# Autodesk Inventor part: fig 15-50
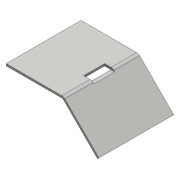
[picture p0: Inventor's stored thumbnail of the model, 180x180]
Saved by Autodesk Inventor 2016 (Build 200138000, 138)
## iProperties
Created: 2015-07
Part Number: fig 15-50
Material: Generic
Document SubType Name: Sheet Metal
Designer: Sandeep
Density: 1 g/cm^3
Sheet Metal Rule: Default_mm
Appearance: Default
Author: Sandeep
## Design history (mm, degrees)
node "Face1"
  sketch "Sketch1"
    geometry: L1 (-9.283, 8.313)-(4.503, 8.313); L2 (4.503, 8.313)-(4.503, -9.63); L3 (4.503, -9.63)-(-9.283, -9.63); L4 (-9.283, -9.63)-(-9.283, 8.313); 1 further point
    constraints: 8 end point, 2 parallel, 1 horizontal, 1 perpendicular
node "Flange1"
sketch "Sketch3"
  geometry: L1 (2.535, 2.162)-(6.789, 2.162); L2 (6.789, 2.162)-(6.789, -2.878); L3 (6.789, -2.878)-(2.535, -2.878); L4 (2.535, -2.878)-(2.535, 2.162); 1 further point
  constraints: 8 end point, 2 parallel, 1 horizontal, 1 perpendicular
cut "Cut1" sketch "Sketch3" dims "d11" = 0.5 (= Thickness), "d12" = 0
body "Solid1"
face "Plate1" dims "Thickness" = 0.5
sketch "Sketch2"
  geometry: L1 through (8.971, 0) direction (-1, 0); L2 through (0, -6) direction (0, -1); L3 (0, -12)-(17.943, -12); L4 (17.943, -12)-(17.943, 0)
  constraints: 6 end point, 1 horizontal, 1 perpendicular, 1 vertical
face "Plate2" dims "d1" = 0.5 (= BendReliefWidth), "d2" = 0.25 (= BendReliefDepth), "d3" = 1 (= MinimumRemnant), "d4" = 0.5 (= BendRadius), "d5" = 12, "d6" = 45 deg, "d7" = 0.5 (= BendRadius), "d8" = 2 (= CornerReliefSize), "d9" = 0.5 (= GapSize), "d10" = 0.5 (= JacobiRadiusSize), "SeamGap" = 0.01, "Thickness" = 0.5
bend "Bend1" dims "d1" = 0.5 (= BendReliefWidth), "d2" = 0.25 (= BendReliefDepth), "d3" = 1 (= MinimumRemnant), "d4" = 0.5 (= BendRadius), "d5" = 12, "d6" = 45 deg, "d7" = 0.5 (= BendRadius), "SeamGap" = 0.01, "Thickness" = 0.5
feature "Corner1" dims "d5" = 12, "d6" = 45 deg, "d8" = 2 (= CornerReliefSize), "d9" = 0.5 (= GapSize), "d10" = 0.5 (= JacobiRadiusSize)
other parameters: "BendRadius" = 0.5 (= Thickness), "BendReliefWidth" = 0.5 (= Thickness), "BendReliefDepth" = 0.25 (= 0.5 x Thickness), "CornerReliefSize" = 2 (= 4 x Thickness), "MinimumRemnant" = 1 (= 2 x Thickness), "TransitionRadius" = 0.5 (= BendRadius), "JacobiRadiusSize" = 0.5 (= BendRadius), "GapSize" = 0.5 (= Thickness), "d0" = 0.5 (= BendRadius)
